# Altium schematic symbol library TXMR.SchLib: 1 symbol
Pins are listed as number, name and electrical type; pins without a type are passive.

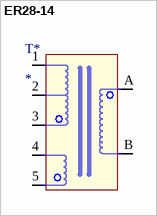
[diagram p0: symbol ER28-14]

## ER28-14
designator T*
footprint ER28-14
pins: 1, 2, 3, 4, 5, A, B
1 alternate drawing of the same symbol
